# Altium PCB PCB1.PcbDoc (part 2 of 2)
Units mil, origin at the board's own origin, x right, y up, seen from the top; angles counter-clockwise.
Board outline 2505 x 2250 mil, 4 copper layers (Top Layer, GND1, GND2, Bottom Layer), stack 23.756 mil thick; 96 components, 62 nets, 306 pads, 129 vias.
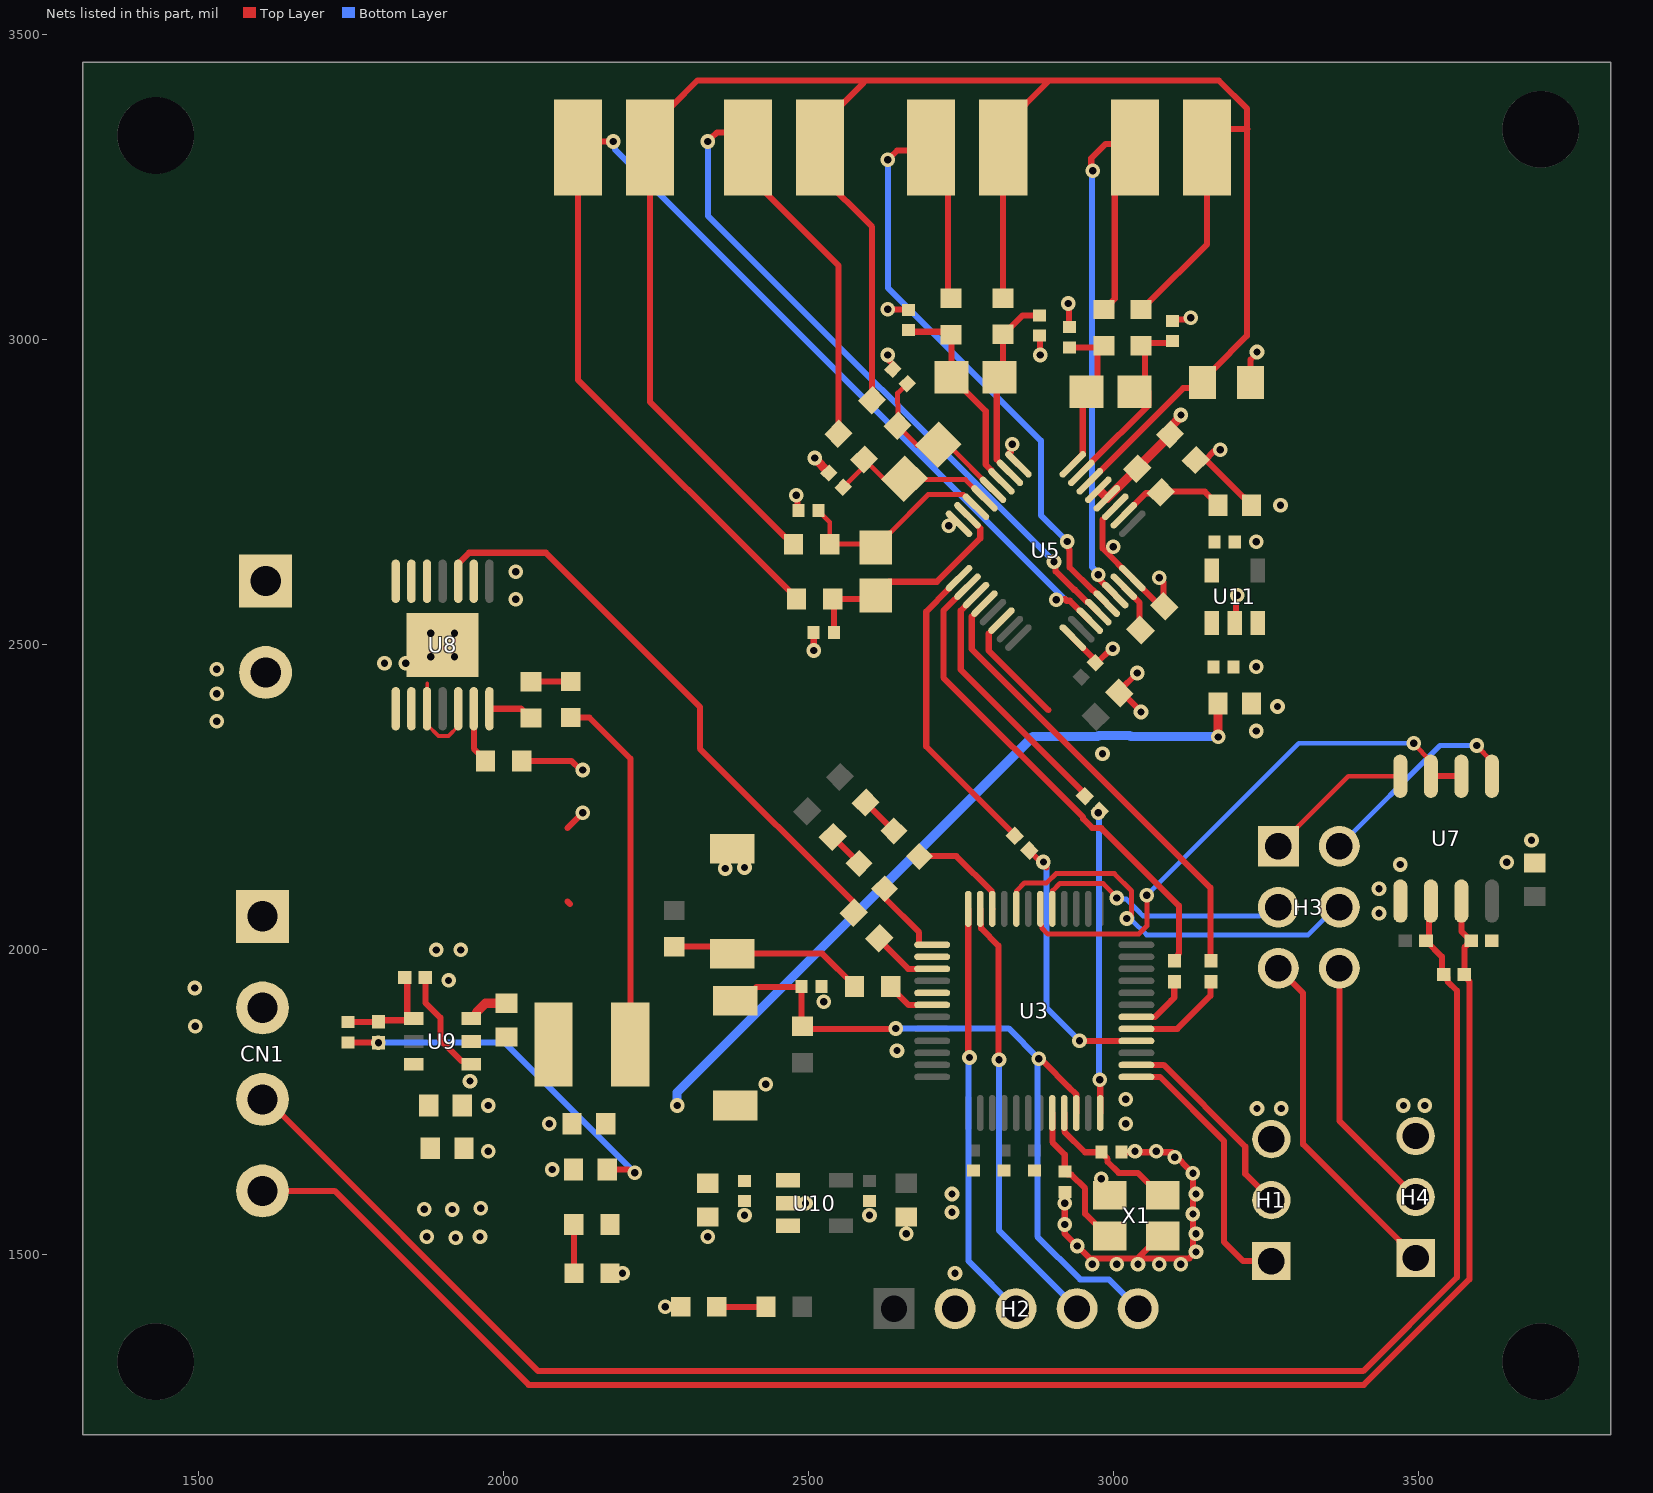
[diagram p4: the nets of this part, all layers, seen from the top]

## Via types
v1: diameter 24, hole 12, Top Layer to Bottom Layer, tented both sides, 125 vias
v2: diameter 24, hole 12, Top Layer to Bottom Layer, 4 vias

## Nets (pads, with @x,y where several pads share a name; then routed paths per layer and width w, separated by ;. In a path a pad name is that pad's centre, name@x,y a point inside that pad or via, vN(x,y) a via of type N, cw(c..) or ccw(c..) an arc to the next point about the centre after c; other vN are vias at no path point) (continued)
5V: C24.2 C25.1 C27.1 C30.2 C31.2 C34.1 C35.1 L1.2 LED2.2 R25.1 R28.2 U10.1 U10.3 U11.1 U11.3 | length 2389.4
  Top Layer w10: C24.2@1745,1848.46 1745.25,1848.21 1794.75,1848.21 v1(1795,1847.96) ; LED2.2@2110.18,2380.81 2140.93,2380.81 2207.99,2313.75 L1.2@2207.99,1845 ; C31.2@2170,1640 v1@2205,1640
  Top Layer w15: C34.1@3170.99,2403.89 3171.21,2403.67 3171.21,2349.33 v1(3171.42,2349.12)
  Bottom Layer w10: v1(1795,1847.96) 2002.04,1847.96 v1(2215,1635)
  Bottom Layer w15: v1@2284.6,1745.4 2284.6,1766.53 2867.8,2349.74 2974.05,2349.74 2975.6,2351.29 3026.48,2351.29 3028.03,2349.74 v1@3167.27,2349.74
  other v1: 2285,1745
485_RX: H3.2 U7.1 | length 344
  Top Layer w8: v1(3595,2335) 3595,2334.29 3620,2309.29 U7.1@3620,2284.73
  Bottom Layer w8: H3.2@3370,2170 3535,2335 v1@3585,2335
485_TX: H3.1 U7.4 | length 247.5
  Top Layer w8: H3.1@3270,2170 3384.73,2284.73 U7.4@3470,2284.73
A: CN1.3 R16.1 R18.2 U7.6 | length 2842.5
  Top Layer w10: CN1.3@1605,1755 1611.54,1755 2056.87,1309.67 3409.06,1309.67 3562.82,1463.43 3562.82,1933.1 3547.05,1948.87 3547.05,1954.37 3541.43,1960 R16.1@3540.92,1960 ; U7.6@3520,2080 3520,2052.59 3517.23,2049.82 3517.23,2020.19 R18.2@3512.04,2015 3537.98,1989.06 R16.1@3537.98,1963.45
A3V3: C4.1 C36.1 C37.1 U5.26 U11.5 | length 177.5
  Top Layer w10: U5.26@3016.61,2712.35 3052.78,2748.52 3076.14,2748.52 C4.1@3077.53,2749.91 3078.92,2751.3 3149.61,2751.3 C37.1@3169.66,2731.25
AIN0: C3.1 C6.2 R1.1 U5.7 | length 385.9
  Top Layer w10: C3.1@2541.54,2520 2541.54,2573.12 R1.1@2539.66,2575 2604.37,2575 C6.2@2610,2580.63 2610,2581.81 2631.57,2603.39 2710.28,2603.39 2781.37,2674.47 2781.37,2691.2 2760.5,2712.07 U5.7@2760.5,2712.35
AIN1: C6.1 C10.1 R2.1 U5.6 | length 348.3
  Top Layer w8: C10.1@2516.54,2720 2516.54,2719.21 2534.66,2701.09 R2.1@2534.66,2665 2604.37,2665 C6.1@2610,2659.37 ; C6.1@2610,2660.55 2632.57,2683.13 2632.8,2683.13 2695.83,2746.15 2753.71,2746.15 2773.59,2726.27 U5.6@2774.41,2726.27
AIN2: C12.1 C13.2 R5.1 U5.5 | length 280.3
  Top Layer w8: C12.1@2556.7,2758.3 2590.97,2792.58 R5.1@2590.97,2795.47 ; R5.1@2590.97,2804.03 2590.97,2798.35 2593.86,2795.47 2594.38,2795.99 2599.73,2795.99 2624.4,2771.33 2656.33,2771.33 2658,2773 2689.92,2773 2692.2,2770.72 2756.99,2770.72 2787.52,2740.19 U5.5@2788.34,2740.19
AIN3: C13.1 C15.1 R8.1 U5.4 | length 275.7
  Top Layer w8: R8.1@2645.97,2859.03 2678,2827 2712,2827 C13.1@2712.84,2827.84 2728.69,2827.84 U5.4@2802.25,2754.27 ; R8.1@2646.77,2859.83 2646.77,2895.21 2645.97,2896.01 2645.97,2912.58 C15.1@2661.7,2928.3
AIN4: C17.1 C18.2 R10.1 U5.3 | length 347.7
  Top Layer w10: C17.1@2663.55,3015.81 2666.22,3013.14 2728.96,3013.14 2734.18,3007.92 C18.2@2734.18,2938.55 ; C18.2@2734.93,2938.55 2735.36,2938.55 2756.94,2916.97 2756.94,2916.54 2790.48,2883 2790.48,2795.37 2799.69,2786.16 2799.69,2784.51 U5.3@2816.17,2768.03
AIN5: C18.1 C19.1 R11.1 U5.2 | length 311.9
  Top Layer w10: R11.1@2818.55,3008.89 2818.55,2939.63 2808.48,2929.56 2808.48,2803.83 2830.09,2782.22 U5.2@2830.09,2781.94 ; R11.1@2819.69,3008.89 2850.89,3040.09 C19.1@2878.55,3040.09
AIN6: C20.1 C22.2 R12.1 U5.32 | length 319.5
  Top Layer w10: C20.1@2927.77,2987.52 2981.5,2987.52 R12.1@2984.32,2990.34 2973.58,2979.6 2973.58,2932.95 2949.38,2908.75 U5.32@2949.38,2812.15 ; U5.32@2933.09,2795.87 U5.32@2949.38,2812.15 ; U5.32@2933.09,2795.87 U5.32@2949.38,2812.15 ; U5.32@2933.09,2795.87 U5.32@2949.38,2812.15
AIN7: C22.1 C23.1 R14.1 U5.31 | length 341
  Top Layer w10: U5.31@2947.08,2782.68 2947.47,2782.68 2963.5,2798.7 2963.5,2799.22 3057.22,2892.95 3057.22,2915 C22.1@3034.37,2915 3051.59,2932.22 3051.59,2983.75 R14.1@3045,2990.34 3049.54,2994.88 3093.83,2994.88 C23.1@3096.72,2997.77
AIN8: R12.2 U5.22 U6.1 | length 1107.6
  Top Layer w10: v1(2965.89,3276.86) 2963.4,3279.36 2963.4,3297.54 2986.49,3320.63 3020.63,3320.63 3025,3325 U6.1@3035,3315 3035,3275.63 3001.94,3242.57 3001.94,3067.28 2996.33,3061.67 2996.33,3060.54 2985.45,3049.66 R12.2@2984.32,3049.66 ; v1(2975,2615) 2975,2609.2 U5.22@3002.69,2581.51
  Bottom Layer w10: v1(2965.89,3276.86) 2964.44,3275.41 2964.44,2628.09 2975,2617.53 v1(2975,2615)
AIN9: R10.2 U4.1 U5.21 | length 1206.6
  Top Layer w10: v1@2635,3300 2645,3310 U4.1@2701.04,3310 ; U4.1@2701.04,3315 2728.65,3287.39 2728.65,3072.77 R10.2@2733.55,3067.87 ; v1@2927.86,2668.69 2926.49,2667.32 2926.49,2657.92 2927.86,2656.55 2927.86,2626.79 2964.64,2590 2966.08,2590 2988.49,2567.58 U5.21@2988.77,2567.58
  Bottom Layer w10: v1(2630,3295) 2630,3085.36 2880.74,2834.62 2880.74,2712.47 v1(2923.81,2669.41)
AIN10: R5.2 U2.1 U5.20 | length 1639
  Top Layer w10: v1@2340,3330 2350,3340 2370.44,3340 2400.44,3310 2400.44,3270.63 2549.03,3122.04 2549.03,2862.95 2549.83,2862.15 2549.83,2846.77 R5.2@2549.03,2845.97 ; v1@2900,2630 2904.58,2630 2905.01,2629.57 2905.01,2620.51 2935.2,2590.32 2936.54,2590.32 2956.71,2570.15 2958.37,2570.15 U5.20@2974.86,2553.67
  Bottom Layer w10: v1(2335,3325) 2335,3203.39 v1(2902.36,2636.04)
AIN11: R1.2 U1.1 U5.19 | length 2049.9
  Top Layer w10: v1@2170,3325 2136.89,3325 2121.89,3310 2121.89,2934.58 2480.34,2576.13 R1.2@2480.34,2575 ; 2920,2575 2922.68,2572.32 2928.36,2572.32 U5.19@2960.93,2539.75
  Bottom Layer w10: v1(2180,3325) 2182.68,3322.32 2182.68,3312.32 2920,2575
  other v1: 2905.93,2574.07
B: CN1.4 R15.1 R16.2 U7.7 | length 2816.2
  Top Layer w10: CN1.4@1605,1605 1723.23,1605 2041.04,1287.2 3410.36,1287.2 3583.11,1459.94 3583.11,1948.51 3581.14,1950.48 3581.14,1954.37 3575.51,1960 R16.2@3575,1960 3575,2004.08 3578.78,2007.87 3578.78,2008.37 R15.1@3585.41,2015 ; U7.7@3570,2080 3570,2030.41 R15.1@3585.41,2015 ; R15.1@3585.92,2015 R15.1@3585.41,2015
BUTTON: R20.1 U3.42 | length 81.2
  Top Layer w10: R20.1@2634.66,1940 2634.66,1938.87 2663.57,1909.96 2702.56,1909.96 U3.42@2702.68,1909.84
CS: R3.1 U3.16 | length 439.3
  Top Layer w10: R3.1@2862.05,2162.95 v1@2890,2135 ; v1(2944.07,1850.87) 2944.11,1850.83 U3.16@3037.32,1850.79 U3.16@3037.32,1850.79
  Bottom Layer w10: v1@2890,2135 2890,1904.94 v1(2944.07,1850.87)
  other v1: 2884.96,2144.03
DE/RE#: U3.30 U7.2 U7.3 | length 919.8
  Top Layer w8: U3.30@2879.84,2067.32 2879.84,2042.4 2882.22,2040.02 2882.22,2035.94 2892.36,2025.79 2985.44,2025.79 2985.8,2026.15 3041.48,2026.15 3054.46,2039.13 v1@3054.46,2088.33 ; v1(3491.75,2338.71) 3491.75,2337.77 3520,2309.52 U7.3@3520,2284.73
  Top Layer w10: U7.3@3520,2284.73 U7.2@3570,2284.73
  Bottom Layer w8: v1(3054.37,2089.53) 3303.55,2338.71 v1(3491.75,2338.71)
DIN: R7.1 U3.18 | length 101.6
  Top Layer w10: U3.18@3037.32,1890.16 3037.44,1890.28 3067.87,1890.28 3094.36,1916.76 3094.36,1916.82 3099.36,1921.83 3099.36,1947.32 R7.1@3100,1947.96
DOUT: R9.1 U3.17 | length 167.5
  Top Layer w10: U3.17@3037.32,1870.47 3037.44,1870.59 3104.36,1870.59 3158.68,1924.9 3158.68,1946.64 R9.1@3160,1947.96
EN: R23.1 U3.39 | length 110
  Top Layer w10: R23.1@2615.97,2019.03 2614.71,2017.77 2663.46,1969.02 2702.56,1969.02 U3.39@2702.68,1968.9
GND: C1.2 C2.2 C3.2 C4.2 C5.1 C7.2 C8.2 C9.2 C10.2 C11.1 C12.2 C14.2 C15.2 C16.1 C17.2 C19.2 C20.2 C21.1 C23.2 C25.2 C26.2 C27.2 C28.2 C30.1 C31.1 C32.1 C33.1 C34.2 C35.2 C36.2 C37.2 CN1.2 H1.3 H2.2 H4.3 LED4.1 LED5.1 P1.2 R13.1 R13.2 R15.2 R17.2 R24.1 R26.2 SW1.1 SW2.1 U5.1 U5.8 U5.14 U5.17 U5.24 U5.27 U5.28 U5.29 U7.5 U8.2 U8.15 U9.4 U10.2 U11.2 X1.2 X1.4 | length 2382.8
  Top Layer w8: U9.4@1934.98,1819.07 1940.77,1819.07 U9.4@1947.25,1812.6
  Top Layer w10: R24.1@1872.04,1955 1872.04,1913.32 1896.49,1888.87 1896.49,1852.49 1930.9,1818.07 1941.77,1818.07 U9.4@1947.25,1812.6 ; R26.2@2029.83,2309.78 2111.43,2309.78 2126.21,2295 v1(2130,2295) ; 2104.99,2079.08 2108.78,2075.29 ; 2104.99,2199.99 v1(2130,2225) ; v1(2480,2745) 2481.73,2743.27 2481.73,2721.73 C10.2@2483.46,2720 ; v1(2508.46,2490.77) C3.2@2508.46,2520 ; v1(2630,2975) 2632.68,2972.32 2632.68,2965.28 2638.86,2959.1 2638.86,2952.25 C15.2@2638.45,2951.85 ; v1(2630,3050) 2630.56,3049.44 2663,3049.44 C17.2@2663.55,3048.89 ; U5.14@2816.17,2539.75 2816.17,2539.47 2795.3,2518.59 2795.3,2490.64 2892.97,2392.97 ; v1@2834.46,2828.75 2831.41,2825.7 2831.41,2816.11 2827.92,2812.63 2827.92,2811.96 U5.1@2844.01,2795.87 ; C19.2@2878.55,3007.01 2879.28,3006.28 2879.28,2975.72 v1(2880,2975) ; C9.2@2920,1603.46 2920,1535 2960.69,1494.31 v1@3039.93,1494.31 ; v1(2925.52,3059.59) 2926.64,3058.47 2926.64,3021.72 C20.2@2927.77,3020.6 ; U5.17@2933.09,2511.91 2933.09,2511.63 2970.25,2474.48 C5.1@2970.25,2470.58 2972.75,2470.58 2996.05,2493.89 v1(2998.55,2493.89) ; U5.27@3002.69,2726.27 3002.69,2725.99 2981.81,2705.11 2981.81,2658.07 U5.24@3030.53,2609.35 3076.51,2563.38 C14.2@3083.04,2563.38 3081.65,2564.77 3081.65,2603.35 v1(3075,2610) ; C11.1@3013,1668.39 3095.75,1668.39 v1(3130,1634.14) 3130,1500.16 3124.14,1494.31 v1@3039.93,1494.31 ; v1(3038.55,2453.89) 3009.43,2424.77 C8.2@3009.43,2421.14 3013.86,2421.14 v1(3045,2390) ; X1.4@3080.49,1530.93 3076.55,1530.93 v1@3039.93,1494.31 ; C23.2@3096.72,3030.85 3099.28,3033.41 3124.01,3033.41 v1(3126.57,3035.97) ; R13.1@3134.53,2802.91 3149.91,2802.91 3164.31,2817.32 3172.32,2817.32 v1(3175,2820) ; R13.1@3135.33,2803.72 3150.71,2803.72 3212.82,2741.6 3215.37,2741.6 3226.11,2730.86 C37.2@3226.11,2728.89 ; U11.2@3198.55,2535.58 3200.7,2537.73 3200.7,2579.29 v1(3202.84,2581.44) ; R17.2@3224.37,2930 3224.37,2967.68 3235,2978.3 v1(3235,2980)
  Top Layer w15: v1(2509.92,2806.38) 2509.92,2805.73 2533.3,2782.35 C12.2@2533.3,2781.7 ; 2980,2750 2988.77,2741.23 U5.28@2988.77,2740.19 2989.31,2740.19 3038.01,2788.89 C4.2@3038.55,2788.89 3038.55,2789.86 3092.58,2843.89 R13.2@3092.58,2844.86 3092.58,2856.47 3110.33,2874.22 v1(3110.33,2876.66)
  other v1: 2265,1415 2195,1470 2740,1470 2965,1485 3005,1485 3040,1485 3075,1485 3110,1485 3135,1505 2940.35,1514.65 1921.46,1528.21 1874.28,1529.74 1961.57,1529.62 2335,1530 2660,1535 3135,1535 2920,1550 2395,1565 2600,1565 3130,1567.15 2735,1570 1915.79,1574.45 1870,1575 1962.51,1576.81 2495,1585 2920,1585 2735,1600 3135,1600 2980,1625 2080,1640 3100,1660 1975,1670 3035,1670 3070,1670 2075,1715 3020,1715 3235,1740 3275,1740 1975,1745 3475,1745 3510,1745 3020,1755 2430,1780 1945,1785 2645,1835 1495,1875 2525,1915 1494.08,1937.69 1910,1950 1890,2000 1930,2000 3435,2060 3435,2100 2363.56,2133.49 2395,2135 3470,2140 3644.46,2143.58 3685,2180 2981.7,2321.3 3233.55,2358.89 1530,2375 3268.55,2398.89 1530,2420 1530,2460 3233.55,2463.89 1805,2470 1840,2470 2020,2575 2020,2620 2999.24,2660.65 3233.55,2668.89 2730,2695 3273.55,2728.89 2834.09,2828.75
  other v2: 1880.67,2480.29 1919.67,2480.28 1880.68,2519.28 1919.67,2519.28
NetC9_1: C9.1 U3.8 X1.3 | length 246.6
  Top Layer w10: U3.8@2899.53,1732.68 2899.53,1685.07 2920,1664.6 C9.1@2920,1636.54 2924.84,1631.7 2930.62,1631.7 2953.31,1609.01 2953.31,1567.55 2985.86,1535 2990,1535 2990,1534.79 X1.3@2993.87,1530.93
NetC11_2: C11.2 U3.9 X1.1 | length 238.3
  Top Layer w10: U3.9@2919.21,1732.68 2919.33,1732.56 2919.33,1702.14 2953.08,1668.39 C11.2@2979.92,1668.39 2979.92,1667.6 2990.16,1657.36 2990.16,1652.37 3008.06,1634.48 3039.93,1634.48 3076.55,1597.86 X1.1@3080.49,1597.86
NetC14_1: C14.1 U5.23 | length 82.4
  Top Layer w10: U5.23@3016.61,2595.42 3016.61,2595.15 3042.67,2569.08 3042.67,2525.79 C14.1@3044.07,2524.4
NetC24_1: C24.1 R24.2 R25.2 U9.1 | length 186.3
  Top Layer w8: C24.1@1745,1881.54 C24.1@1745.25,1881.79 ; R25.2@1794.75,1881.79 R25.2@1795,1882.04 R25.2@1797.68,1884.72 ; R24.2@1837.96,1955 R24.2@1842.18,1950.78 ; U9.1@1842.18,1893.87 1848.65,1887.4 U9.1@1852.75,1887.4 U9.1@1850.07,1884.72
  Top Layer w10: C24.1@1745.25,1881.79 R25.2@1794.75,1881.79 ; R25.2@1797.68,1884.72 U9.1@1850.07,1884.72 ; U9.1@1842.18,1893.87 R24.2@1842.18,1950.78
NetC29_1: C29.1 L1.1 U9.5
NetC29_2: C29.2 U9.6 | length 72.4
  Top Layer w15: U9.6@1947.25,1887.4 1952.52,1887.4 1955.49,1890.37 1955.49,1897.51 1970.54,1912.56 C29.2@2005,1912.56
NetLED1_2: LED1.2 R21.1 | length 65.9
  Top Layer w10: R21.1@2593.44,2241.57 LED1.2@2640,2195
NetLED2_1: LED2.1 R22.2 | length 65.1
  Top Layer w10: R22.2@2045.17,2439.44 2045.51,2439.78 LED2.1@2110.17,2439.78
NetLED3_2: LED3.2 R27.1 | length 61.2
  Top Layer w10: R27.1@2539.77,2185.23 LED3.2@2583.04,2141.96
NetLED4_2: LED4.2 R28.1 | length 80.1
  Top Layer w10: R28.1@2115.34,1550 2115.34,1470.17 LED4.2@2115.51,1469.99
NetLED5_2: LED5.2 R29.1 | length 80.9
  Top Layer w10: LED5.2@2349.49,1415.01 R29.1@2430.34,1415
NetR3_2: R3.2 U5.9 | length 504.6
  Top Layer w10: U5.9@2746.57,2609.35 2730.09,2592.86 2730.09,2591.69 2692.87,2554.47 2692.87,2333.43 2837.95,2188.34 R3.2@2837.95,2187.05
NetR4_2: R4.2 U5.11 | length 424.1
  Top Layer w10: U5.11@2774.42,2581.5 2774.42,2581.22 2749.46,2556.26 2749.46,2459.32 2952.95,2255.83 R4.2@2952.95,2252.05
NetR7_2: R7.2 U5.10 | length 801.3
  Top Layer w10: U5.10@2760.5,2595.42 2721.07,2556 2721.07,2446.38 2950,2217.45 2950,2214.64 2964.64,2200 2971.58,2200 2972.02,2199.56 2980,2199.56 3107.1,2072.47 3107.1,1994.03 3105.63,1992.56 3105.63,1987.67 R7.2@3100,1982.04
NetR9_2: R9.2 U5.12 | length 756.8
  Top Layer w10: U5.12@2788.34,2567.58 2788.34,2567.31 2767.46,2546.43 2767.46,2493.03 3158.63,2101.86 3158.63,1983.41 R9.2@3160,1982.04
NetR19_1: R19.1 R20.2 SW2.2 | length 323.1
  Top Layer w10: R19.1@2280,2005.34 2363.64,2005.34 SW2.2@2375,1993.98 2522.49,1993.98 2575.34,1941.13 R20.2@2575.34,1940
NetR22_1: R22.1 U8.14 | length 74.5
  Top Layer w10: U8.14@1976.94,2395.27 2028.89,2395.27 2044.04,2380.12 R22.1@2045.17,2380.12
NetR23_2: R23.2 U8.3 | length 979.4
  Top Layer w10: U8.3@1925.76,2604.29 1925.76,2633.01 1943.65,2650.9 2069.4,2650.9 2322,2398.3 2322,2329.98 2574.83,2077.15 2574.83,2061.77 R23.2@2574.03,2060.97
NetR26_1: R26.1 U8.13 | length 93.4
  Top Layer w10: U8.13@1951.35,2395.27 1951.35,2330.08 1970.51,2310.92 R26.1@1970.51,2309.78
NRST: C16.2 H2.5 R6.1 SW1.2 U3.10 | length 1202.9
  Top Layer w10: SW1.2@2380,1917.04 2392.4,1917.04 2414.42,1939.06 2483.62,1939.06 2484.56,1940 C16.2@2488.46,1940 2488.46,1876.2 2494.47,1870.19 2641.66,1870.19 v1(2642.78,1871.31) ; v1@2886.27,1815.57 2926.63,1775.21 2926.8,1775.21 2938.78,1763.22 2938.78,1732.8 U3.10@2938.9,1732.68
  Bottom Layer w10: v1(2642.78,1871.31) 2827.96,1871.31 v1(2877.47,1821.77) ; v1@2875,1819.98 2875,1530 2945,1460 2992.2,1460 H2.5@3040.05,1412.16
PA12: LED1.1 U3.34 | length 171.3
  Top Layer w10: LED1.1@2682.22,2153.82 2696.39,2153.82 2696.91,2153.3 2697.42,2153.82 2742.21,2153.82 2800.98,2095.05 2800.98,2067.44 U3.34@2801.1,2067.32
PA15: LED3.1 U3.37 | length 136.7
  Top Layer w10: LED3.1@2624.75,2100.26 2624.75,2085.06 2681.22,2028.59 2681.22,2008.56 2681.51,2008.27 U3.37@2702.68,2008.27
PD0: U3.38
PD3: U3.41
REFP0: R2.2 R8.2 R11.2 R14.2 R17.1 U1.2 U2.2 U4.2 U5.30 U6.2 | length 3908.7
  Top Layer w10: R2.2@2475.34,2665 2475.34,2666.13 2464.46,2677.01 2461.3,2677.01 2240,2898.31 2240,3349.37 2274.37,3383.74 2276.4,3383.74 2317.66,3425 2590,3425 ; R8.2@2604.03,2900.97 2604.83,2901.77 2604.83,2917.15 2604.03,2917.95 2604.03,3185.15 2518.55,3270.63 2518.55,3349.37 2590,3420.82 2590,3425 ; R11.2@2818.55,3068.21 2818.55,3314.41 U4.2@2819.15,3315 2819.15,3349.37 2894.78,3425 2895,3425 ; U5.30@2961.41,2768.03 2961.41,2768.23 2978.01,2784.83 2978.21,2784.83 3114.19,2920.81 3132.58,2920.81 R17.1@3145.63,2933.85 ; R14.2@3045,3049.66 3055.88,3060.54 3057.12,3060.54 3153.11,3156.53 U6.2@3153.11,3315 3183.37,3345.26 3219.41,3345.26 ; R17.1@3145.63,2934.81 3162.92,2952.11 3163.84,2952.11 3218.4,3006.67 3218.4,3345.26 ; 3218.91,3345.26 3218.91,3378.68 3172.59,3425 2895,3425 ; 2590,3425 2895,3425
SCLK: R4.1 U3.12 | length 493.7
  Top Layer w10: v1(2977.04,1786.96) 2978.15,1785.85 2978.15,1732.8 U3.12@2978.27,1732.68
  Bottom Layer w10: v1(2975,2225) 2976.02,2223.98 2976.02,1787.98 v1(2977.04,1786.96)
SWCLK: H2.3 U3.36 | length 688.8
  Top Layer w10: U3.36@2761.73,2067.32 2761.73,1825.76 v1(2763.73,1823.77)
  Bottom Layer w10: v1(2763.73,1823.77) 2762.29,1822.33 2762.29,1489.91 H2.3@2840.05,1412.16
SWDIO: H2.4 U3.35 | length 712.1
  Top Layer w10: U3.35@2781.42,2067.32 2781.42,2042.94 2782.78,2041.57 2782.78,2035.52 2811.2,2007.11 v1@2811.2,1823.93
  Bottom Layer w10: v1@2812.25,1815.64 2812.25,1539.95 H2.4@2940.05,1412.16
  other v1: 2812.25,1819.89
TTL_RX: H3.6 H4.2 | length 426.8
  Top Layer w10: H3.6@3370,1970 3370,1720 H4.2@3495,1595
TTL_TX: H3.5 H4.1 | length 568.5
  Top Layer w10: H3.5@3270,1970 3310.68,1929.32 3310.68,1681.53 3468.5,1523.71 3468.5,1521 3494.5,1495 H4.1@3495,1495
USART1_RX: H3.4 U3.32 | length 657.7
  Top Layer w8: U3.32@2840.47,2067.32 2840.97,2067.82 2840.97,2096.83 2854,2109.86 2890.42,2109.86 2905.51,2124.95 3001.16,2124.95 3029.52,2096.6 v1@3029.52,2053.67
  Bottom Layer w8: v1@3030.03,2052.99 3030.03,2048.71 3054.2,2024.54 3318.69,2024.54 3364.16,2070 H3.4@3370,2070
  other v1: 3021.72,2051.41
USART1_TX: H3.3 U3.29 | length 423.4
  Top Layer w8: U3.29@2899.53,2067.32 2900.03,2067.82 2900.03,2097.19 2911.69,2108.85 2982.58,2108.85 2984.58,2106.85 2993.59,2097.88 ; 2993.59,2097.84 v1@2998.74,2092.68
  Bottom Layer w8: v1@3005.52,2085.52 3007.89,2083.15 3021.09,2083.15 3043.72,2060.52 3043.72,2060.21 3048.4,2055.52 3239.58,2055.52 3254.05,2070 H3.3@3270,2070
  other v1: 3005,2085
USART2_RX: H1.2 U3.14 | length 339.2
  Top Layer w10: U3.14@3037.32,1811.42 3081.85,1811.42 3215.71,1677.56 3215.71,1632.99 H1.2@3258.69,1590
USART2_TX: H1.1 U3.13 | length 443.4
  Top Layer w10: U3.13@3037.32,1791.73 3076.08,1791.73 3181.16,1686.65 3181.16,1521.04 3212.2,1490 H1.1@3258.69,1490
VIN: C32.2 C33.2 CN1.1 U8.8 U8.9 U8.10 U8.12 U9.3 | length 161.6
  Top Layer w6: 1875,2437.12 1875,2369.26 1893.59,2350.66 1909.87,2350.66 1925.76,2366.55 U8.12@1925.76,2395.27
VOUT: P1.1 U8.5 U8.6 U8.7
pads on no net: *1.1 *2.1 *3.1 *4.1 U3.1 U3.2 U3.3 U3.7 U3.11 U3.15 U3.19 U3.20 U3.21 U3.22 U3.23 U3.24 U3.25 U3.26 U3.27 U3.28 U3.31 U3.33 U3.40 U3.43 U3.44 U3.45 U3.46 U3.47 U3.48 U5.13 U5.25 U8.1 U8.4 U8.11 U9.2 U10.4 U11.4
copper on no net:
  other v1: 2938.37,2715.36

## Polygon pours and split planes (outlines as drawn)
VIN on Top Layer "NONET_L-01_P-001" (hatched Horizontal grid 4 track 5, remove dead copper, pour order 45): 1535,1960 1650,1960 1675,1935 1675,1705 1795,1705 1855,1645 1910,1645 1910,1765 1875,1800 1875,1835 1720,1835 1715,1830 1710,1835 1710,2181.46 1885.39,2356.86 1885,2357.25 1885,2440 1795,2440 1535,2180 1535,2175
GND on Top Layer "NONET_L-01_P-001" (hatched Horizontal grid 4 track 5, remove dead copper, pour order 46): 1315,3452.07 1315,1219.93 3810,1219.93 3810,3452.07
VOUT on Top Layer "NONET_L-01_P-001" (hatched Horizontal grid 4 track 5, remove dead copper, pour order 5): 1885.17,2694.78 1885.17,2569.78 1870.17,2554.78 1535.17,2554.78 1535.17,2694.78 1555.17,2704.78 1560.17,2709.78 1845.17,2709.78
NetC29_1 on Top Layer "NONET_L-01_P-001" (hatched Horizontal grid 4 track 5, remove dead copper, pour order 1): 1925,1875 1925,1830 1970,1830 2040,1760 2125,1760 2145,1780 2145,1935 2040,1935 2040,1890 1995,1890 1980,1875
5V on Top Layer "NONET_L-01_P-001" (hatched Horizontal grid 4 track 5, remove dead copper, pour order 18): 3138.55,2373.89 3143.55,2368.89 3203.55,2368.89 3203.55,2428.89 3178.55,2453.89 3178.55,2498.89 3268.55,2498.89 3268.55,2558.89 3228.55,2558.89 3218.55,2558.89 3218.55,2518.89 3183.55,2518.89 3178.55,2523.89 3178.55,2568.89 3138.55,2568.89 3133.55,2563.89 3133.55,2418.89
5V on Top Layer "NONET_L-01_P-001" (hatched Horizontal grid 4 track 5, remove dead copper, pour order 14): 2160,1940 2155,1935 2155,1745 2145,1735 2145,1510 2225,1510 2310,1595 2370,1595 2370,1600 2380,1610 2420,1610 2420,1520 2425,1515 2505,1515 2505,1560 2495,1570 2440,1570 2440,1595 2445,1600 2500,1600 2500,1655 2375,1780 2270,1780 2270,1940
A3V3 on Top Layer "NONET_L-01_P-001" (hatched Horizontal grid 4 track 5, remove dead copper, pour order 42): 3140,2595 3185,2595 3185,2695 3190,2700 3190,2770 3145,2770 3140,2765
5V on Top Layer "NONET_L-01_P-001" (hatched Horizontal grid 4 track 5, remove dead copper, pour order 41): 3200,2325 3195,2330 3195,2440 3180,2455 3180,2495 3260,2495 3275,2510 3270,2515 3270,2565 3215,2565 3215,2500 3190,2500 3180,2510 3185,2515 3185,2565 3140,2565 3135,2560 3140,2555 3140,2325
5V on Top Layer "NONET_L-01_P-001" (hatched Horizontal grid 4 track 5, remove dead copper, pour order 39): 2165,1935 2160,1930 2160,1755 2155,1755 2140,1740 2145,1735 2145,1510 2235,1510 2240,1505 2330,1595 2425,1595 2430,1590 2430,1525 2500,1525 2500,1565 2455,1565 2450,1570 2450,1605 2485,1605 2490,1610 2490,1690 2245,1935
3V3 on Top Layer "NONET_L-01_P-001" (hatched Horizontal grid 4 track 5, remove dead copper, pour order 22): 2983.55,2348.89 3013.55,2378.89 3013.55,2388.89 3011.05,2388.89 2958.55,2441.39 2958.55,2458.89 2858.55,2553.89 2803.55,2513.89 2803.55,2503.89 2963.55,2343.89
3V3 on Top Layer "NONET_L-01_P-001" (hatched Horizontal grid 4 track 5, remove dead copper, pour order 3): 2515,1650 2520,1645 2520,1595 2570,1595 2585,1610 2615,1610 2635,1590 2700,1590 2700,1605 2755,1660 2890,1660 2890,1690 2885,1695 2870,1695 2870,1780 2810,1780 2810,1700 2805,1695 2720,1695 2680,1655
GND on Bottom Layer "NONET_L-01_P-001" (hatched Horizontal grid 4 track 5, remove dead copper, pour order 37): 1315,3450 1315,1222.24 3805,1222.24 3805,3450
GND on GND1 "NONET_L-01_P-001" (hatched Horizontal grid 4 track 5, remove dead copper, pour order 44): 1320,3455 1320,1217.5 3805,1217.5 3805,3455
GND on GND2 "NONET_L-01_P-001" (hatched Horizontal grid 4 track 5, remove dead copper, pour order 43): 1315,3450 1315,1217.5 3805,1217.5 3805,3450

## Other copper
Top Layer:
  pour cut-out: 2028.96,3456.04 2040,3445 2040,2790.44 2434.4,2396.04 2873.96,2396.04 2873.96,2401.04 3118.96,2646.04 3118.96,2851.04 3230.6,2851.04 3468.96,3089.4 3468.96,3446.04 3463.96,3451.04
  pour cut-out: 3590,1440 3590,1220 3810,1220 3810,1440
  pour cut-out: 1315,1440 1315,1220 1535,1220 1535,1440
  pour cut-out: 3590,3455 3590,3235 3810,3235 3810,3455
  pour cut-out: 1320,3450 1320,3230 1540,3230 1540,3450
  pour cut-out: 2905,1620 2905,1525 2960,1470 3125,1470 3125,1475 3155,1505 3150,1510 3150,1640 3145,1640 3095,1690 3005,1690
GND1:
  pour cut-out: 3585,1430 3585,1210 3805,1210 3805,1430
  pour cut-out: 1320,1440 1320,1220 1540,1220 1540,1440
  pour cut-out: 1320,3450 1320,3230 1540,3230 1540,3450
  pour cut-out: 3590,3455 3590,3235 3810,3235 3810,3455
GND2:
  pour cut-out: 3590,1430 3590,1210 3810,1210 3810,1430
  pour cut-out: 1315,1435 1315,1215 1535,1215 1535,1435
  pour cut-out: 1320,3450 1320,3230 1540,3230 1540,3450
  pour cut-out: 3585,3460 3585,3240 3805,3240 3805,3460
Bottom Layer:
  pour cut-out: 3590,3455 3590,3235 3810,3235 3810,3455
  pour cut-out: 1320,3450 1320,3230 1540,3230 1540,3450
  pour cut-out: 1320,1435 1320,1215 1540,1215 1540,1435
  pour cut-out: 3590,1435 3590,1215 3810,1215 3810,1435

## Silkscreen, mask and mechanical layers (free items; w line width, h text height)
Top Overlay:
  text "1+" at 2095,3410 h30
  text "1-" at 2220,3410 h30
  text "2+" at 2390,3410 h30
  text "2-" at 2505,3410 h30
  text "3+" at 2685,3410 h30
  text "3-" at 2795,3410 h30
  text "4+" at 3015,3410 h30
  text "4-" at 3130,3410 h30
  text "ADS124S08_RTD_Acq" at 1475,3125 h30
  text "Ver1.0" at 1480,3060 h30
  text "2026/9/8" at 1480,3000 h30
  text "VOUT+" at 1555,2720 h30
  text "GND" at 1580,2315 h30
  text "485" at 3216.39,2251.78 h30
  text "485" at 3331.39,2251.78 h30
  text "VIN+" at 1685,2100 h30
  text "FLT" at 2171.66,2031.98 h30
  text "GND" at 1690,1965 h30
  text "TTL" at 3210,1865 h30
  text "TTL" at 3340,1865 h30
  text "RST" at 2305,1755 h30 r90
  text "A" at 1685,1735 h30
  text "GND" at 3330,1675 h30
  text "GND" at 3579.68,1670 h30
  text "B" at 1692.51,1586.66 h30
  text "RX1" at 3581.57,1576.65 h30
  text "RX2" at 3330,1575 h30
  text "TX1" at 3581.92,1476.23 h30
  text "TX2" at 3330,1470 h30
  text "5VLED" at 1960,1450 h30
  text "3V3LED" at 2255.17,1343.34 h30
  text "3V3" at 2580.52,1310.3 h30
  text "GND" at 2690,1310.3 h30
  text "CLK" at 2815.52,1310.3 h30
  text "DIO" at 2925.52,1310.3 h30
  text "RST" at 3030.52,1310.3 h30
Mechanical 1:
  the board outline again, w10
